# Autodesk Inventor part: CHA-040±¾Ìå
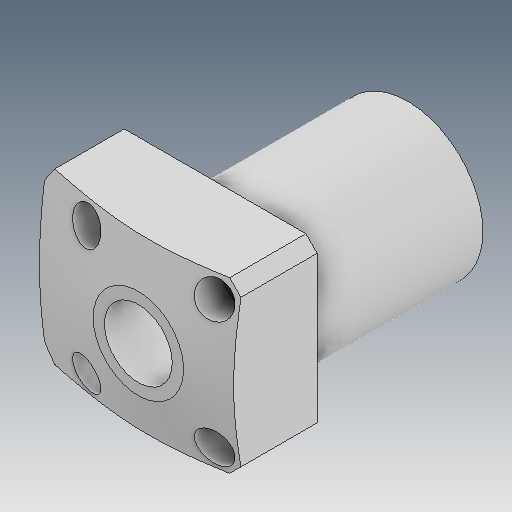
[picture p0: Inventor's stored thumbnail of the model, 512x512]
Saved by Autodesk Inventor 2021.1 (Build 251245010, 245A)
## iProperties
Created: 2019-05
Part Number: CHA-040±¾Ìå
Material: Ogólny
Document SubType Name: Modeling
Designer: user
Density: 1 g/cm^3
Appearance: Domyślna
Author: user
Revision Number: ÈÎºÎ
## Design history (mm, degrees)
feature "ÊäÈë1"
node "Bryła1"
